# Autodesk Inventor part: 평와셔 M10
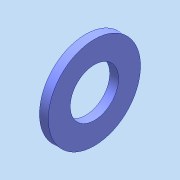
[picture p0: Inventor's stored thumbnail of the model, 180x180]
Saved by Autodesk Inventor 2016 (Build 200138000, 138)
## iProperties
Created: 2024-08
Part Number: 평와셔 M10
Material: 일반
Description: 평면 와셔
Document SubType Name: Modeling
Designer: pc-7
Density: 1 g/cm^3
Appearance: 기본값
Author: jhkim
Sending System: Autodesk Inventor 2025
Preprocessor: ST-DEVELOPER v20
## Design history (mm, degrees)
node "평와셔 M101"
node "솔리드1"
body "Solid1"
